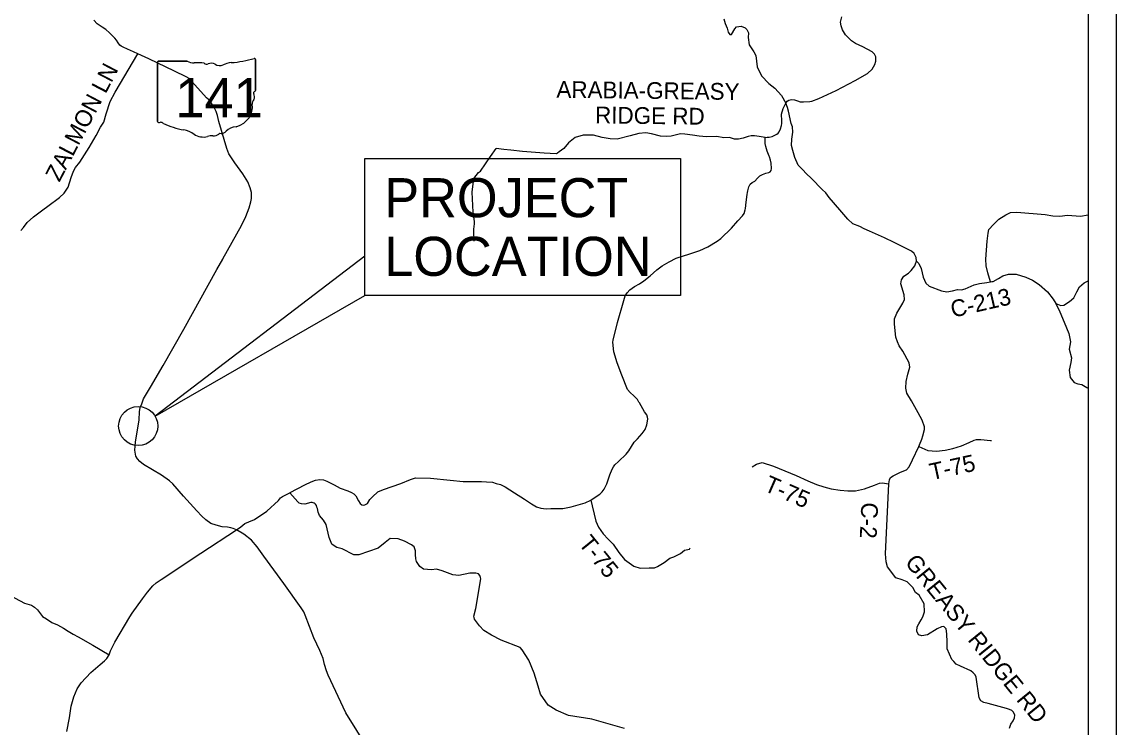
# Model space of a CAD drawing. Extents: x -6.4 to 34, y -1.2 to 22.
# Drawn here: x 5.084 to 9, y 16.922 to 19.448 of the extents above; entities that cross this region are included whole.
import ezdxf

# ---------------------------------------------------------------- set-up
doc = ezdxf.new("R2010")
doc.units = 0
for name, color, linetype in [('GM_X_County_ROW', 7, 'Continuous'), ('GM_X_Minor_Lake', 7, 'Continuous'), ('GM_X_Minor_River', 7, 'Continuous'), ('GM_X_Minor_River_Text', 7, 'Continuous'), ('GM_X_Township', 7, 'Continuous'), ('GM_X_Township_Road', 7, 'Continuous'), ('GM_X_Township_Subdivision', 7, 'Continuous'), ('GM_X_Township_Text', 7, 'Continuous')]:
    doc.layers.add(name, color=color, linetype=linetype)

msp = doc.modelspace()

# ---------------------------------------------------------------- linework, layer by layer
at = {"layer": 'GM_X_County_ROW'}
for p, q in [((5.6755, 19.3075), (5.5729, 19.3075)), ((5.9196, 19.2015), (5.9196, 19.3127)), ((5.5695, 19.3038), (5.5695, 19.0912)), ((5.9196, 19.2016), (5.9196, 19.2015))]:
    msp.add_line(p, q, dxfattribs=at)
for centre, major_axis, start_param, end_param in [((5.5735, 19.3043), (0.00406, 0), 1.712693, 3.28349), ((5.6999, 19.3321), (0.0393, 0), 4.042523, 4.731795), ((5.7949, 19.5973), (0.3713, 0), 4.814394, 5.042369), ((5.9157, 19.3132), (0.0039, 0), 6.141152, 7.989035), ((5.7129, 19.1881), (0.1412, 0), 1.404758, 1.657858), ((5.745, 19.3054), (0.0113, 0), 3.836095, 5.185415), ((5.7617, 19.2808), (0.0236, 0), 0.950623, 2.079405), ((5.7921, 19.3145), (0.0284, 0), 4.081561, 5.145723), ((5.8422, 19.2425), (0.0747, 0), 1.699011, 2.107814), ((5.9187, 19.1934), (0.00603, 0), 1.883978, 3.671073), ((5.8803, 19.1793), (0.0362, 0), 5.934695, 6.695948), ((5.9154, 19.2011), (0.00417, 0), 5.05454, 6.418171), ((5.8157, 19.1408), (0.0929, 0), 5.101752, 6.440018), ((5.9336, 19.155), (0.0263, 0), 2.387724, 3.262537), ((5.5735, 19.0908), (0.00409, 0), 3.00124, 4.508301), ((5.5742, 19.1125), (0.0312, 0), 4.665946, 4.897461), ((5.5806, 19.079), (0.0113, 0), 0.519207, 1.627899), ((5.7227, 19.27), (0.2681, 0), 4.195997, 4.488961), ((5.8548, 19.0316), (0.0509, 0), 1.647645, 2.488434), ((5.6428, 18.9957), (0.0839, 0), 0.823519, 1.323587), ((5.7335, 19.0779), (0.0532, 0), 4.026481, 4.996735), ((5.7643, 19.0044), (0.0437, 0), 1.495662, 1.94098), ((5.7681, 19.062), (0.0284, 0), 4.691044, 5.507374), ((5.7938, 19.0414), (0.00798, 0), 1.147584, 2.315152), ((5.7904, 19.0706), (0.03, 0), 4.937069, 5.64225)]:
    msp.add_ellipse(centre, major_axis=major_axis, ratio=0.8, start_param=start_param, end_param=end_param, dxfattribs=at)
at = {"layer": 'GM_X_Minor_Lake'}
for points in [[(7.7585, 18.9665), (7.7514, 18.9852), (7.7459, 19.0016), (7.7442, 19.0123), (7.7439, 19.021), (7.7439, 19.024), (7.7437, 19.0339), (7.7509, 19.0342), (7.7585, 19.0348), (7.7696, 19.0373), (7.7856, 19.0454), (7.7902, 19.0496), (7.7941, 19.0541), (7.7992, 19.065), (7.8027, 19.0767), (7.8036, 19.0843), (7.8033, 19.0915), (7.8031, 19.1021), (7.8028, 19.1086), (7.8029, 19.1173), (7.8089, 19.1377), (7.8175, 19.1566), (7.823, 19.1641), (7.8287, 19.1674), (7.8382, 19.1696), (7.8492, 19.169), (7.8597, 19.1647), (7.8696, 19.1619), (7.8817, 19.161), (7.9033, 19.1622), (7.9113, 19.1636), (7.9361, 19.1734), (7.9975, 19.2021), (8.0663, 19.2376), (8.1103, 19.2631), (8.1264, 19.2784), (8.1369, 19.2954), (8.1405, 19.3075), (8.1396, 19.3231), (8.1355, 19.3318), (8.1269, 19.3399), (8.0934, 19.3583), (8.0667, 19.3708), (8.0528, 19.3801), (8.0319, 19.4017), (8.0212, 19.4193), (8.0157, 19.4331), (8.014, 19.4471), (8.0188, 19.4653)], [(5.9026, 18.8027), (5.9028, 18.8035), (5.906, 18.8151), (5.9052, 18.8368), (5.9013, 18.8532), (5.8921, 18.8742), (5.8744, 18.9033), (5.8465, 18.9424), (5.8335, 18.9608), (5.8246, 18.9746), (5.8173, 18.9941), (5.7891, 19.0909), (5.7838, 19.1126), (5.7787, 19.1272), (5.7702, 19.1436), (5.7561, 19.1651), (5.7501, 19.171), (5.7449, 19.1762), (5.6923, 19.234), (5.6822, 19.2444), (5.6717, 19.251), (5.6299, 19.2717), (5.5377, 19.3148), (5.4989, 19.3329), (5.4831, 19.3407), (5.462, 19.3505), (5.4461, 19.3572), (5.439, 19.3603), (5.4345, 19.3642), (5.4278, 19.3726), (5.4222, 19.3818), (5.4163, 19.3895), (5.3976, 19.4091), (5.3845, 19.4207), (5.371, 19.4293), (5.3537, 19.4409), (5.3414, 19.4536)], [(7.6728, 18.7749), (7.674, 18.7787), (7.6755, 18.8015), (7.6801, 18.8291), (7.6808, 18.8361), (7.6814, 18.8431), (7.685, 18.8571), (7.6897, 18.8665), (7.6978, 18.8729), (7.7066, 18.8769), (7.7169, 18.8874), (7.7243, 18.8964), (7.7342, 18.9012), (7.7468, 18.9059), (7.7567, 18.9081), (7.762, 18.9103), (7.7659, 18.9148), (7.7671, 18.9223), (7.7659, 18.9413), (7.7626, 18.9524), (7.7594, 18.9642), (7.7585, 18.9665)], [(5.8025, 18.5981), (5.803, 18.599), (5.8701, 18.7188), (5.8854, 18.7505), (5.8969, 18.7822), (5.9026, 18.8027)], [(7.3214, 18.0108), (7.3245, 18.0254), (7.3231, 18.0322), (7.3202, 18.0398), (7.3124, 18.0513), (7.2939, 18.0827), (7.2924, 18.085), (7.2872, 18.095), (7.2742, 18.1081), (7.2611, 18.12), (7.2514, 18.1308), (7.2305, 18.1827), (7.2137, 18.2259), (7.2021, 18.2655), (7.1992, 18.3001), (7.1997, 18.3073), (7.2158, 18.3709), (7.2378, 18.4495), (7.2434, 18.4661), (7.2496, 18.4774), (7.2596, 18.4875), (7.2765, 18.4998), (7.2944, 18.5094), (7.3101, 18.5202), (7.332, 18.5381), (7.3562, 18.5598), (7.375, 18.5735), (7.3998, 18.5887), (7.4258, 18.6013), (7.4742, 18.6173), (7.51, 18.6289), (7.539, 18.6425), (7.5719, 18.6618), (7.5857, 18.6714), (7.6237, 18.7085), (7.6461, 18.7351), (7.663, 18.7527), (7.6685, 18.7609), (7.6728, 18.7749)], [(5.8516, 17.6287), (5.8403, 17.6336), (5.8315, 17.6351), (5.8202, 17.6373), (5.8011, 17.6395), (5.7789, 17.6444), (5.7604, 17.6512), (5.7424, 17.6646), (5.7276, 17.6775), (5.7104, 17.6962), (5.6619, 17.749), (5.6239, 17.7927), (5.6124, 17.8036), (5.5836, 17.8235), (5.5195, 17.8627), (5.5056, 17.8732), (5.4974, 17.8824), (5.4919, 17.8927), (5.4876, 17.9137), (5.4903, 17.9417), (5.5037, 18.0224), (5.5052, 18.0504), (5.5077, 18.0662), (5.5126, 18.0794), (5.519, 18.0972), (5.5436, 18.1395), (5.5893, 18.2172), (5.6634, 18.3476), (5.7818, 18.5611), (5.8025, 18.5981)], [(6.6796, 17.8013), (6.7062, 17.8013), (6.7283, 17.8018), (6.747, 17.8007), (6.7683, 17.7987), (6.7816, 17.7946), (6.797, 17.791), (6.8134, 17.7825), (6.8469, 17.7607), (6.8832, 17.7377), (6.908, 17.7208), (6.9256, 17.7112), (6.9415, 17.7055), (6.9597, 17.7038), (6.9767, 17.7049), (7.0201, 17.7045), (7.05, 17.7101), (7.1002, 17.7253), (7.1205, 17.7349), (7.1354, 17.7449), (7.1523, 17.7564), (7.1603, 17.7639), (7.1681, 17.7744), (7.1767, 17.7929), (7.1878, 17.8258), (7.1968, 17.845), (7.2007, 17.8541), (7.2061, 17.8608), (7.2188, 17.8735), (7.2461, 17.8997), (7.2557, 17.9113), (7.2748, 17.9422), (7.2867, 17.9538), (7.3037, 17.9737), (7.3145, 17.9879), (7.32, 18.0045), (7.3214, 18.0108)], [(5.8516, 17.6287), (5.8673, 17.6393), (5.8822, 17.6512), (5.8964, 17.6571), (5.9158, 17.6651), (5.9602, 17.6956), (6.0021, 17.7333), (6.0091, 17.7424), (6.016, 17.7479), (6.0236, 17.7509), (6.0423, 17.7605), (6.0438, 17.7616), (6.0966, 17.7897), (6.1191, 17.8007), (6.1351, 17.8058), (6.1507, 17.8086), (6.1628, 17.8073), (6.1752, 17.8022), (6.2019, 17.7889), (6.2226, 17.7776), (6.2502, 17.768), (6.263, 17.7625), (6.272, 17.7575), (6.2791, 17.7498), (6.2891, 17.7322), (6.295, 17.723), (6.3002, 17.718), (6.3051, 17.7164), (6.3112, 17.7174), (6.3206, 17.7222), (6.3286, 17.7374), (6.3382, 17.747), (6.3572, 17.7639), (6.3782, 17.7731), (6.4399, 17.794), (6.4751, 17.8082), (6.4926, 17.814), (6.5465, 17.8131), (6.6163, 17.8067), (6.6628, 17.8013), (6.6796, 17.8013)], [(5.2446, 16.9056), (5.2543, 16.9547), (5.2607, 16.9971), (5.2695, 17.0295), (5.2821, 17.0591), (5.2959, 17.08), (5.3307, 17.1174), (5.3641, 17.1461), (5.3799, 17.1594), (5.3881, 17.1679), (5.3965, 17.181), (5.4014, 17.1953), (5.4166, 17.226), (5.4703, 17.3168), (5.4787, 17.3303), (5.5155, 17.3807), (5.5337, 17.4055), (5.553, 17.4276), (5.5649, 17.438), (5.5821, 17.4507), (5.7241, 17.5446), (5.8516, 17.6287)], [(6.3215, 16.8466), (6.2435, 16.9728), (6.1804, 17.108), (6.1737, 17.1236), (6.1673, 17.1455), (6.162, 17.1675), (6.15, 17.1958), (6.1285, 17.2416), (6.0982, 17.323), (6.0924, 17.335), (6.0832, 17.3485), (6.0214, 17.4356), (5.9493, 17.5334), (5.9257, 17.5673), (5.9052, 17.5908), (5.8786, 17.6124), (5.8516, 17.6287)]]:
    msp.add_lwpolyline(points, dxfattribs=at)
at = {"layer": 'GM_X_Minor_River'}
for points in [[(8.2824, 18.5813), (8.2853, 18.5904), (8.2845, 18.6033), (8.2772, 18.6177), (8.2677, 18.6268), (8.2555, 18.6324), (8.2058, 18.6569), (8.1708, 18.6746), (8.1176, 18.6978), (8.0982, 18.7065), (8.083, 18.7148), (8.0572, 18.7241), (8.04, 18.7415), (8.0114, 18.7748), (7.9733, 18.8191), (7.9611, 18.8353), (7.9477, 18.847), (7.91, 18.8864), (7.8902, 18.9041), (7.8787, 18.9181), (7.8616, 18.9347), (7.8504, 18.962), (7.8431, 18.9867), (7.8377, 19.0049), (7.8398, 19.0277), (7.8431, 19.0531), (7.8415, 19.0714), (7.8376, 19.0843), (7.8279, 19.1283), (7.8236, 19.1415), (7.8175, 19.1566)], [(8.6179, 16.9174), (8.6233, 16.9322), (8.6313, 16.9436), (8.6363, 16.955), (8.6371, 16.9648), (8.6326, 16.9747), (8.6262, 16.9808), (8.6183, 16.985), (8.6073, 16.9881), (8.5422, 17.0056), (8.5267, 17.0102), (8.5161, 17.0156), (8.5104, 17.0266), (8.4991, 17.1003), (8.4954, 17.1087), (8.4886, 17.1163), (8.4803, 17.1228), (8.4425, 17.1401), (8.4281, 17.1474), (8.4187, 17.1562), (8.4115, 17.1638), (8.3958, 17.2015), (8.3952, 17.2262), (8.3942, 17.2558), (8.392, 17.2737), (8.3837, 17.2825), (8.3746, 17.281), (8.3594, 17.2739), (8.3244, 17.2524), (8.305, 17.2491), (8.2926, 17.2525), (8.2873, 17.2647), (8.2878, 17.2807), (8.2935, 17.292), (8.302, 17.3053), (8.3077, 17.3167), (8.3145, 17.3343), (8.3136, 17.3635), (8.2956, 17.3945), (8.2826, 17.4036), (8.2723, 17.4214), (8.2517, 17.4418), (8.2346, 17.4493), (8.2111, 17.4568), (8.1821, 17.4958), (8.177, 17.5132), (8.175, 17.5417), (8.1868, 17.7932), (8.1894, 17.8076), (8.1928, 17.8156), (8.2018, 17.8217), (8.2287, 17.8348), (8.2498, 17.8428), (8.2592, 17.8543), (8.2716, 17.8786), (8.294, 17.9265), (8.2967, 17.9323), (8.3045, 17.9525), (8.3079, 17.9646), (8.3142, 17.9878), (8.3137, 17.9977), (8.306, 18.0216), (8.2915, 18.047), (8.2681, 18.0898), (8.2513, 18.1182), (8.2474, 18.1356), (8.2484, 18.1592), (8.2547, 18.1854), (8.2617, 18.2105), (8.2598, 18.2268), (8.2372, 18.2677), (8.223, 18.2874), (8.2173, 18.3011), (8.2111, 18.3189), (8.207, 18.3648), (8.2069, 18.3846), (8.2148, 18.4047), (8.2366, 18.4402), (8.2425, 18.4535), (8.2417, 18.4702), (8.2301, 18.51), (8.2319, 18.5241), (8.2406, 18.5363), (8.2564, 18.5477), (8.267, 18.5577), (8.2801, 18.5744), (8.2823, 18.581), (8.2824, 18.5813)], [(8.2853, 18.5904), (8.2941, 18.5825), (8.3018, 18.5647), (8.3099, 18.5339), (8.3195, 18.5116), (8.3306, 18.5006), (8.3746, 18.4845), (8.394, 18.4804), (8.4144, 18.4839), (8.4326, 18.4893), (8.4466, 18.4882), (8.4595, 18.4913), (8.4916, 18.5056), (8.5105, 18.511), (8.537, 18.5141), (8.5509, 18.5165), (8.5548, 18.5172), (8.5552, 18.5172)], [(8.5552, 18.5172), (8.5598, 18.518), (8.579, 18.5287), (8.5949, 18.5379), (8.6153, 18.5437), (8.6419, 18.5442), (8.6772, 18.5334), (8.7003, 18.5229), (8.7247, 18.507), (8.7544, 18.4802), (8.7742, 18.4549), (8.7838, 18.4386), (8.7991, 18.409), (8.8145, 18.3726), (8.831, 18.3317), (8.8373, 18.3021), (8.8339, 18.2884), (8.8321, 18.2759), (8.8399, 18.244), (8.8381, 18.228), (8.8322, 18.1999), (8.835, 18.1737), (8.8495, 18.1559), (8.8624, 18.1511), (8.8768, 18.1489), (8.8954, 18.1383), (8.9, 18.1359)]]:
    msp.add_lwpolyline(points, dxfattribs=at)
at = {"layer": 'GM_X_Minor_River_Text'}
for points in [[(7.5956, 19.4591), (7.6013, 19.4416), (7.6079, 19.4257), (7.6117, 19.4113), (7.6171, 19.4022), (7.6232, 19.403), (7.6352, 19.4232), (7.6416, 19.4297), (7.6579, 19.4328), (7.6723, 19.4264), (7.6788, 19.4204), (7.6841, 19.409), (7.6835, 19.3915), (7.6863, 19.3653), (7.7035, 19.34), (7.7108, 19.3275), (7.7148, 19.2872), (7.7305, 19.2539), (7.7572, 19.2274), (7.7785, 19.2101), (7.8022, 19.184), (7.8175, 19.1566)], [(5.0795, 18.7), (5.089, 18.7114), (5.1024, 18.7288), (5.1248, 18.7493), (5.1583, 18.7747), (5.1765, 18.7875), (5.2187, 18.8182), (5.2354, 18.8345), (5.2492, 18.8554), (5.2602, 18.8899), (5.2686, 18.9135), (5.2759, 18.926), (5.2907, 18.9449), (5.3243, 18.9977), (5.3494, 19.0409), (5.3654, 19.0705), (5.3772, 19.0887), (5.3856, 19.1187), (5.3998, 19.1628), (5.4177, 19.1954), (5.4989, 19.3329)], [(7.7437, 19.0339), (7.7227, 19.0366), (7.7052, 19.0392), (7.6938, 19.0395), (7.6832, 19.0376), (7.6658, 19.0314), (7.648, 19.0279), (7.6348, 19.0274), (7.6166, 19.0331), (7.5957, 19.0322), (7.5707, 19.0374), (7.5343, 19.0361), (7.5081, 19.0382), (7.4839, 19.0419), (7.4562, 19.0456), (7.4406, 19.0466), (7.4073, 19.0385), (7.3891, 19.0373), (7.3698, 19.0387), (7.3372, 19.0469), (7.3163, 19.0502), (7.2917, 19.0478), (7.2603, 19.04), (7.2145, 19.028), (7.1898, 19.0287), (7.1606, 19.0335), (7.1295, 19.0417), (7.0924, 19.0415), (7.0636, 19.0338), (7.0402, 19.0147), (7.0233, 18.9941), (7.0067, 18.9826), (7.001, 18.9769), (6.996, 18.9747), (6.9529, 18.9778), (6.8754, 18.9834), (6.8341, 18.9885), (6.8088, 18.991), (6.7812, 18.9936)], [(6.7027, 18.6617), (6.7014, 18.6975), (6.7013, 18.7), (6.7014, 18.7019), (6.7014, 18.7036), (6.7016, 18.7058), (6.7032, 18.7249), (6.7034, 18.7265), (6.7034, 18.728), (6.7034, 18.7292), (6.7033, 18.7304), (6.7033, 18.7315), (6.7031, 18.7329), (6.6996, 18.758), (6.6994, 18.7591), (6.6992, 18.7606), (6.699, 18.763), (6.6988, 18.7648), (6.6987, 18.7665), (6.695, 18.8372), (6.701, 18.8866), (6.7175, 18.9084), (6.7251, 18.9134), (6.7614, 18.9652), (6.7812, 18.9936)], [(8.5509, 18.5165), (8.5411, 18.5489), (8.5351, 18.5743), (8.534, 18.5979), (8.5363, 18.6298), (8.5387, 18.6621), (8.5418, 18.691), (8.5449, 18.7043), (8.5608, 18.7221), (8.5806, 18.7414), (8.6057, 18.7569), (8.622, 18.7652), (8.6444, 18.7667), (8.7457, 18.7581), (8.7738, 18.7535), (8.7989, 18.7523), (8.8262, 18.7548), (8.8721, 18.7524), (8.9, 18.7562)], [(8.7838, 18.4386), (8.8019, 18.4323), (8.8133, 18.4327), (8.8331, 18.4459), (8.8483, 18.4596), (8.8589, 18.4812), (8.8688, 18.4983), (8.8852, 18.5134), (8.9, 18.5196)], [(8.294, 17.9265), (8.3259, 17.9126), (8.3566, 17.9102), (8.3885, 17.9136), (8.4151, 17.9192), (8.4462, 17.9297), (8.4736, 17.9415), (8.4918, 17.9494), (8.5002, 17.9524), (8.5161, 17.9524), (8.5506, 17.9485), (8.5537, 17.9478)], [(7.6978, 17.8543), (7.7132, 17.8632), (7.7338, 17.8692), (7.774, 17.8569), (7.8551, 17.8225), (7.8972, 17.8042), (7.9275, 17.7901), (7.954, 17.7824), (7.9798, 17.7755), (8.0121, 17.7705), (8.0398, 17.7674), (8.0675, 17.7677), (8.099, 17.7752), (8.1351, 17.788), (8.1533, 17.7952), (8.1632, 17.7963), (8.1868, 17.7932)], [(7.24, 16.917), (7.1241, 16.9504), (7.0404, 16.9633), (6.996, 16.9827), (6.9677, 17.0006), (6.9404, 17.0397), (6.931, 17.0677), (6.9173, 17.1144), (6.8985, 17.1618), (6.8745, 17.1987), (6.8673, 17.2065), (6.7992, 17.2325), (6.765, 17.2508), (6.7374, 17.2677), (6.7215, 17.2844), (6.7041, 17.3077), (6.7023, 17.3144), (6.7014, 17.3195), (6.708, 17.3464), (6.7267, 17.4529), (6.7257, 17.4574), (6.723, 17.4642), (6.7174, 17.4701), (6.7083, 17.4729), (6.6874, 17.4726), (6.6474, 17.465), (6.6259, 17.4671), (6.5884, 17.4819), (6.5682, 17.4878), (6.5495, 17.4855), (6.535, 17.4862), (6.5217, 17.4872), (6.508, 17.497), (6.4958, 17.5149), (6.494, 17.5249), (6.4922, 17.5401), (6.492, 17.5534), (6.4882, 17.5669), (6.4826, 17.5712), (6.4779, 17.5748), (6.4528, 17.5876), (6.4303, 17.5957), (6.402, 17.5969), (6.3837, 17.583), (6.3592, 17.5628), (6.2895, 17.5382), (6.2845, 17.5382), (6.2713, 17.5383), (6.2304, 17.5598), (6.2107, 17.5655), (6.1984, 17.5734), (6.1934, 17.5766), (6.1838, 17.6005), (6.1723, 17.647), (6.1629, 17.6624), (6.149, 17.6799), (6.1447, 17.6917), (6.1415, 17.7052), (6.1399, 17.7098), (6.1377, 17.7157), (6.1343, 17.7197), (6.1306, 17.7238), (6.1293, 17.7243), (6.1228, 17.7262), (6.1211, 17.7265), (6.1179, 17.7256), (6.0959, 17.7207), (6.0845, 17.7217), (6.076, 17.724), (6.0713, 17.728), (6.0423, 17.7605)], [(7.1205, 17.7349), (7.125, 17.7148), (7.1322, 17.684), (7.1374, 17.6597), (7.1476, 17.638), (7.1639, 17.6136), (7.1824, 17.5954), (7.1998, 17.5775), (7.2199, 17.5466), (7.2411, 17.5219), (7.2744, 17.4987), (7.2968, 17.4906), (7.3283, 17.4917), (7.3477, 17.4924), (7.359, 17.4966), (7.3819, 17.5109), (7.4028, 17.5265), (7.4172, 17.5314), (7.4404, 17.5435), (7.4548, 17.5552), (7.4731, 17.559), (7.476, 17.5636)], [(5.026, 17.4018), (5.0934, 17.3655), (5.1177, 17.3579), (5.1287, 17.3514), (5.1393, 17.3415), (5.1575, 17.3175), (5.1722, 17.3092), (5.1904, 17.2966), (5.2116, 17.2885), (5.2331, 17.2762), (5.2493, 17.2655), (5.2671, 17.254), (5.2856, 17.2448), (5.3374, 17.2157), (5.3965, 17.181)]]:
    msp.add_lwpolyline(points, dxfattribs=at)
at = {"layer": 'GM_X_Township'}
for p, q in [((9, 21), (9, 14)), ((8.9, 20.9), (8.9, 14.1))]:
    msp.add_line(p, q, dxfattribs=at)
for points in [[(6.3106, 18.958), (7.4406, 18.958), (7.4406, 18.468), (6.3106, 18.468)], [(6.3106, 18.468), (6.3106, 18.608), (5.5606, 18.035)]]:
    msp.add_lwpolyline(points, close=True, dxfattribs=at)
msp.add_circle((5.5, 18), 0.07, dxfattribs=at)
at = {"layer": 'GM_X_Township_Road'}
for p, q in [((5.5729, 19.3075), (5.6755, 19.3075)), ((5.9196, 19.3127), (5.9196, 19.2015)), ((5.5695, 19.0912), (5.5695, 19.3038)), ((5.9168, 19.198), (5.9168, 19.198))]:
    msp.add_line(p, q, dxfattribs=at)
msp.add_lwpolyline([(6.3106, 18.958), (7.4406, 18.958), (7.4406, 18.468), (6.3106, 18.468)], close=True, dxfattribs=at)
for centre, major_axis, start_param, end_param in [((5.5735, 19.3043), (0.00406, 0), 1.712693, 3.28349), ((5.6999, 19.3321), (0.0393, 0), 4.042523, 4.731795), ((5.7949, 19.5973), (0.3713, 0), 4.814394, 5.042369), ((5.9157, 19.3132), (0.0039, 0), 6.141152, 7.989035), ((5.7129, 19.1881), (0.1412, 0), 1.404758, 1.657858), ((5.745, 19.3054), (0.0113, 0), 3.836095, 5.185415), ((5.7617, 19.2808), (0.0236, 0), 0.950623, 2.079405), ((5.7921, 19.3145), (0.0284, 0), 4.081561, 5.145723), ((5.8422, 19.2425), (0.0747, 0), 1.699011, 2.107814), ((5.9187, 19.1934), (0.00603, 0), 1.883978, 3.671073), ((5.8803, 19.1793), (0.0362, 0), 5.934695, 6.695948), ((5.9154, 19.2011), (0.00417, 0), 5.05454, 6.418171), ((5.8157, 19.1408), (0.0929, 0), 5.101752, 6.440018), ((5.9336, 19.155), (0.0263, 0), 2.387724, 3.262537), ((5.5735, 19.0908), (0.00409, 0), 3.00124, 4.508301), ((5.5742, 19.1125), (0.0312, 0), 4.665946, 4.897461), ((5.5806, 19.079), (0.0113, 0), 0.519207, 1.627899), ((5.7227, 19.27), (0.2681, 0), 4.195997, 4.488961), ((5.8548, 19.0316), (0.0509, 0), 1.647645, 2.488434), ((5.6428, 18.9957), (0.0839, 0), 0.823519, 1.323587), ((5.7335, 19.0779), (0.0532, 0), 4.026481, 4.996735), ((5.7643, 19.0044), (0.0437, 0), 1.495662, 1.94098), ((5.7681, 19.062), (0.0284, 0), 4.691044, 5.507374), ((5.7938, 19.0414), (0.00798, 0), 1.147584, 2.315152), ((5.7904, 19.0706), (0.03, 0), 4.937069, 5.64225)]:
    msp.add_ellipse(centre, major_axis=major_axis, ratio=0.8, start_param=start_param, end_param=end_param, dxfattribs=at)

# ---------------------------------------------------------------- texts
at = {"layer": 'GM_X_County_ROW'}
msp.add_text('141', height=0.14004, dxfattribs=at).set_placement((5.6334, 19.1062))
at = {"layer": 'GM_X_Township'}
for s, p in [('PROJECT', (6.3806, 18.748)), ('LOCATION', (6.3806, 18.538))]:
    msp.add_text(s, height=0.14, dxfattribs=at).set_placement(p)
at = {"layer": 'GM_X_Township_Subdivision'}
for s, rotation, p in [('ZALMON LN', 62.3918, (5.2181, 18.8716)), ('T-75', 12.2989, (8.3395, 17.8056)), ('T-75', 336.4692, (7.736, 17.7698)), ('T-75', 308.8333, (7.0736, 17.5784))]:
    msp.add_text(s, height=0.06, rotation=rotation, dxfattribs=at).set_placement(p)
at = {"layer": 'GM_X_Township_Text'}
for s, rotation, p in [('ARABIA-GREASY', 359.2761, (6.9966, 19.1762)), ('RIDGE RD', 359.2761, (7.1349, 19.0844)), ('C-213', 12.9548, (8.4153, 18.3878)), ('C-2', 267.3063, (8.0886, 17.7277)), ('GREASY RIDGE RD', 309.0801, (8.2414, 17.5104))]:
    msp.add_text(s, height=0.06, rotation=rotation, dxfattribs=at).set_placement(p)

doc.saveas('drawing.dxf')
